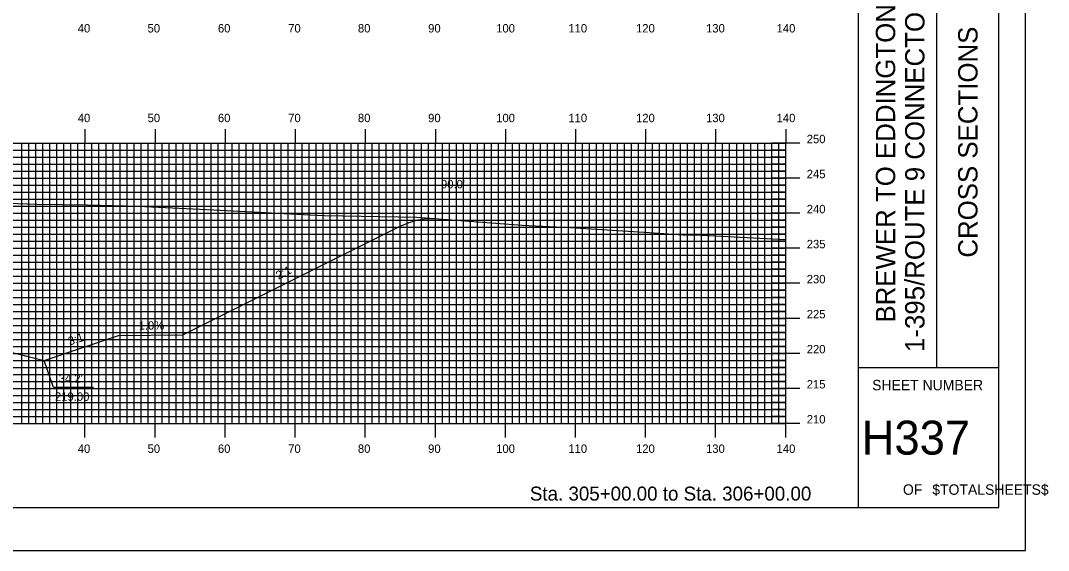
# Model space of a CAD drawing. Extents: x 1816883 to 1817226, y 442591 to 442811.
# Drawn here: x 1817079.4 to 1817226.1, y 442590.5 to 442666.2 of the extents above; entities that cross this region are included whole.
import ezdxf

# ---------------------------------------------------------------- set-up
doc = ezdxf.new("R2010")
doc.units = 0
for name, color, linetype in [('ANNOTATION', 7, 'Continuous'), ('BORDER', 7, 'Continuous'), ('D_Roadway_Centerline', 7, 'Continuous'), ('D_Roadway_SlopeLines', 7, 'Continuous'), ('D_Text_Standard', 7, 'Continuous'), ('H_V ANNOTATION', 7, 'Continuous'), ('MAJOR', 7, 'Continuous'), ('MINOR', 7, 'Continuous'), ('PLOT BOUNDARY', 7, 'Continuous'), ('S_Roadway_Centerline', 7, 'Continuous')]:
    doc.layers.add(name, color=color, linetype=linetype)

msp = doc.modelspace()

# ---------------------------------------------------------------- linework, layer by layer
at = {"layer": 'ANNOTATION'}
msp.add_lwpolyline([(1817089.8, 442613.78), (1817084.1, 442613.78), (1817082.76, 442617.67)], dxfattribs=at)
at = {"layer": 'BORDER'}
for p, q in [((1817198.99, 442596.67), (1817198.99, 442806.67)), ((1817210.17, 442616.67), (1817210.17, 442686.67)), ((1817198.99, 442616.67), (1817218.99, 442616.67))]:
    msp.add_line(p, q, dxfattribs=at)
msp.add_lwpolyline([(1816898.99, 442596.67), (1817218.99, 442596.67), (1817218.99, 442806.67), (1816898.99, 442806.67)], close=True, dxfattribs=at)
at = {"layer": 'D_Roadway_Centerline'}
msp.add_lwpolyline([(1816958.59, 442642.2), (1816959.84, 442642.08), (1816961.09, 442641.81), (1816962.34, 442641.41), (1816963.59, 442640.85), (1817002.86, 442621.22), (1817003.78, 442621.21), (1817014.41, 442617.67), (1817018.41, 442618.67), (1817028.59, 442621.21), (1817036.59, 442621.53), (1817048.59, 442621.77), (1817060.59, 442621.53), (1817068.59, 442621.21), (1817078.76, 442618.67), (1817082.76, 442617.67), (1817093.39, 442621.21), (1817102.53, 442621.3), (1817133.59, 442636.83), (1817134.84, 442637.37), (1817136.09, 442637.72), (1817137.34, 442637.9), (1817138.59, 442637.9)], dxfattribs=at)
at = {"layer": 'D_Roadway_SlopeLines'}
for points in [[(1817093.39, 442621.21), (1817102.53, 442621.3), (1817133.59, 442636.83), (1817134.84, 442637.37), (1817136.09, 442637.72), (1817137.34, 442637.9), (1817138.59, 442637.9)], [(1817068.59, 442621.21), (1817082.76, 442617.67)], [(1817082.76, 442617.67), (1817093.39, 442621.21)]]:
    msp.add_lwpolyline(points, dxfattribs=at)
at = {"layer": 'MAJOR'}
for p, q in [((1817088.59, 442650.67), (1817088.59, 442648.67)), ((1817098.59, 442650.67), (1817098.59, 442648.67)), ((1817108.59, 442650.67), (1817108.59, 442648.67)), ((1817118.59, 442650.67), (1817118.59, 442648.67)), ((1817128.59, 442650.67), (1817128.59, 442648.67)), ((1817138.59, 442650.67), (1817138.59, 442648.67)), ((1817148.59, 442650.67), (1817148.59, 442648.67)), ((1817158.59, 442650.67), (1817158.59, 442648.67)), ((1817168.59, 442650.67), (1817168.59, 442648.67)), ((1817178.59, 442650.67), (1817178.59, 442648.67)), ((1817188.59, 442650.67), (1817188.59, 442648.67)), ((1816908.59, 442648.67), (1817188.59, 442648.67)), ((1816908.59, 442648.67), (1817188.59, 442648.67)), ((1817088.59, 442608.67), (1817088.59, 442648.67)), ((1817098.59, 442608.67), (1817098.59, 442648.67)), ((1817108.59, 442608.67), (1817108.59, 442648.67)), ((1817118.59, 442608.67), (1817118.59, 442648.67)), ((1817128.59, 442608.67), (1817128.59, 442648.67)), ((1817138.59, 442608.67), (1817138.59, 442648.67)), ((1817148.59, 442608.67), (1817148.59, 442648.67)), ((1817158.59, 442608.67), (1817158.59, 442648.67)), ((1817168.59, 442608.67), (1817168.59, 442648.67)), ((1817178.59, 442608.67), (1817178.59, 442648.67)), ((1817190.59, 442648.67), (1817186.58, 442648.67)), ((1817188.59, 442608.67), (1817188.59, 442648.67)), ((1817188.59, 442608.67), (1817188.59, 442648.67)), ((1816908.59, 442643.67), (1817188.59, 442643.67)), ((1817190.59, 442643.67), (1817186.58, 442643.67)), ((1816908.59, 442638.67), (1817188.59, 442638.67)), ((1817190.59, 442638.67), (1817186.58, 442638.67)), ((1816908.59, 442633.67), (1817188.59, 442633.67)), ((1817190.59, 442633.67), (1817186.58, 442633.67)), ((1816908.59, 442628.67), (1817188.59, 442628.67)), ((1817190.59, 442628.67), (1817186.58, 442628.67)), ((1816908.59, 442623.67), (1817188.59, 442623.67)), ((1817190.59, 442623.67), (1817186.58, 442623.67)), ((1816908.59, 442618.67), (1817188.59, 442618.67)), ((1817190.59, 442618.67), (1817186.58, 442618.67)), ((1816908.59, 442613.67), (1817188.59, 442613.67)), ((1817190.59, 442613.67), (1817186.58, 442613.67)), ((1816908.59, 442608.67), (1817188.59, 442608.67)), ((1816908.59, 442608.67), (1817188.59, 442608.67)), ((1817088.59, 442606.66), (1817088.59, 442608.67)), ((1817098.59, 442606.66), (1817098.59, 442608.67)), ((1817108.59, 442606.66), (1817108.59, 442608.67)), ((1817118.59, 442606.66), (1817118.59, 442608.67)), ((1817128.59, 442606.66), (1817128.59, 442608.67)), ((1817138.59, 442606.66), (1817138.59, 442608.67)), ((1817148.59, 442606.66), (1817148.59, 442608.67)), ((1817158.59, 442606.66), (1817158.59, 442608.67)), ((1817168.59, 442606.66), (1817168.59, 442608.67)), ((1817178.59, 442606.66), (1817178.59, 442608.67)), ((1817190.59, 442608.67), (1817186.58, 442608.67)), ((1817188.59, 442606.66), (1817188.59, 442608.67))]:
    msp.add_line(p, q, dxfattribs=at)
at = {"layer": 'MINOR'}
for p, q in [((1817079.59, 442608.67), (1817079.59, 442648.67)), ((1817080.59, 442608.67), (1817080.59, 442648.67)), ((1817081.59, 442608.67), (1817081.59, 442648.67)), ((1817082.59, 442608.67), (1817082.59, 442648.67)), ((1817083.59, 442608.67), (1817083.59, 442648.67)), ((1817084.59, 442608.67), (1817084.59, 442648.67)), ((1817085.59, 442608.67), (1817085.59, 442648.67)), ((1817086.59, 442608.67), (1817086.59, 442648.67)), ((1817087.59, 442608.67), (1817087.59, 442648.67)), ((1817089.59, 442608.67), (1817089.59, 442648.67)), ((1817090.59, 442608.67), (1817090.59, 442648.67)), ((1817091.59, 442608.67), (1817091.59, 442648.67)), ((1817092.59, 442608.67), (1817092.59, 442648.67)), ((1817093.59, 442608.67), (1817093.59, 442648.67)), ((1817094.59, 442608.67), (1817094.59, 442648.67)), ((1817095.59, 442608.67), (1817095.59, 442648.67)), ((1817096.59, 442608.67), (1817096.59, 442648.67)), ((1817097.59, 442608.67), (1817097.59, 442648.67)), ((1817099.59, 442608.67), (1817099.59, 442648.67)), ((1817100.59, 442608.67), (1817100.59, 442648.67)), ((1817101.59, 442608.67), (1817101.59, 442648.67)), ((1817102.59, 442608.67), (1817102.59, 442648.67)), ((1817103.59, 442608.67), (1817103.59, 442648.67)), ((1817104.59, 442608.67), (1817104.59, 442648.67)), ((1817105.59, 442608.67), (1817105.59, 442648.67)), ((1817106.59, 442608.67), (1817106.59, 442648.67)), ((1817107.59, 442608.67), (1817107.59, 442648.67)), ((1817109.59, 442608.67), (1817109.59, 442648.67)), ((1817110.59, 442608.67), (1817110.59, 442648.67)), ((1817111.59, 442608.67), (1817111.59, 442648.67)), ((1817112.59, 442608.67), (1817112.59, 442648.67)), ((1817113.59, 442608.67), (1817113.59, 442648.67)), ((1817114.59, 442608.67), (1817114.59, 442648.67)), ((1817115.59, 442608.67), (1817115.59, 442648.67)), ((1817116.59, 442608.67), (1817116.59, 442648.67)), ((1817117.59, 442608.67), (1817117.59, 442648.67)), ((1817119.59, 442608.67), (1817119.59, 442648.67)), ((1817120.59, 442608.67), (1817120.59, 442648.67)), ((1817121.59, 442608.67), (1817121.59, 442648.67)), ((1817122.59, 442608.67), (1817122.59, 442648.67)), ((1817123.59, 442608.67), (1817123.59, 442648.67)), ((1817124.59, 442608.67), (1817124.59, 442648.67)), ((1817125.59, 442608.67), (1817125.59, 442648.67)), ((1817126.59, 442608.67), (1817126.59, 442648.67)), ((1817127.59, 442608.67), (1817127.59, 442648.67)), ((1817129.59, 442608.67), (1817129.59, 442648.67)), ((1817130.59, 442608.67), (1817130.59, 442648.67)), ((1817131.59, 442608.67), (1817131.59, 442648.67)), ((1817132.59, 442608.67), (1817132.59, 442648.67)), ((1817133.59, 442608.67), (1817133.59, 442648.67)), ((1817134.59, 442608.67), (1817134.59, 442648.67)), ((1817135.59, 442608.67), (1817135.59, 442648.67)), ((1817136.59, 442608.67), (1817136.59, 442648.67)), ((1817137.59, 442608.67), (1817137.59, 442648.67)), ((1817139.59, 442608.67), (1817139.59, 442648.67)), ((1817140.59, 442608.67), (1817140.59, 442648.67)), ((1817141.59, 442608.67), (1817141.59, 442648.67)), ((1817142.59, 442608.67), (1817142.59, 442648.67)), ((1817143.59, 442608.67), (1817143.59, 442648.67)), ((1817144.59, 442608.67), (1817144.59, 442648.67)), ((1817145.59, 442608.67), (1817145.59, 442648.67)), ((1817146.59, 442608.67), (1817146.59, 442648.67)), ((1817147.59, 442608.67), (1817147.59, 442648.67)), ((1817149.59, 442608.67), (1817149.59, 442648.67)), ((1817150.59, 442608.67), (1817150.59, 442648.67)), ((1817151.59, 442608.67), (1817151.59, 442648.67)), ((1817152.59, 442608.67), (1817152.59, 442648.67)), ((1817153.59, 442608.67), (1817153.59, 442648.67)), ((1817154.59, 442608.67), (1817154.59, 442648.67)), ((1817155.59, 442608.67), (1817155.59, 442648.67)), ((1817156.59, 442608.67), (1817156.59, 442648.67)), ((1817157.59, 442608.67), (1817157.59, 442648.67)), ((1817159.59, 442608.67), (1817159.59, 442648.67)), ((1817160.59, 442608.67), (1817160.59, 442648.67)), ((1817161.59, 442608.67), (1817161.59, 442648.67)), ((1817162.59, 442608.67), (1817162.59, 442648.67)), ((1817163.59, 442608.67), (1817163.59, 442648.67)), ((1817164.59, 442608.67), (1817164.59, 442648.67)), ((1817165.59, 442608.67), (1817165.59, 442648.67)), ((1817166.59, 442608.67), (1817166.59, 442648.67)), ((1817167.59, 442608.67), (1817167.59, 442648.67)), ((1817169.59, 442608.67), (1817169.59, 442648.67)), ((1817170.59, 442608.67), (1817170.59, 442648.67)), ((1817171.59, 442608.67), (1817171.59, 442648.67)), ((1817172.59, 442608.67), (1817172.59, 442648.67)), ((1817173.59, 442608.67), (1817173.59, 442648.67)), ((1817174.59, 442608.67), (1817174.59, 442648.67)), ((1817175.59, 442608.67), (1817175.59, 442648.67)), ((1817176.59, 442608.67), (1817176.59, 442648.67)), ((1817177.59, 442608.67), (1817177.59, 442648.67)), ((1817179.59, 442608.67), (1817179.59, 442648.67)), ((1817180.59, 442608.67), (1817180.59, 442648.67)), ((1817181.59, 442608.67), (1817181.59, 442648.67)), ((1817182.59, 442608.67), (1817182.59, 442648.67)), ((1817183.59, 442608.67), (1817183.59, 442648.67)), ((1817184.59, 442608.67), (1817184.59, 442648.67)), ((1817185.59, 442608.67), (1817185.59, 442648.67)), ((1817186.59, 442608.67), (1817186.59, 442648.67)), ((1817187.59, 442608.67), (1817187.59, 442648.67)), ((1816908.59, 442647.67), (1817188.59, 442647.67)), ((1816908.59, 442646.67), (1817188.59, 442646.67)), ((1817188.59, 442647.67), (1817186.58, 442647.67)), ((1817188.59, 442646.67), (1817186.58, 442646.67)), ((1816908.59, 442645.67), (1817188.59, 442645.67)), ((1817188.59, 442645.67), (1817186.58, 442645.67)), ((1816908.59, 442644.67), (1817188.59, 442644.67)), ((1817188.59, 442644.67), (1817186.58, 442644.67)), ((1816908.59, 442642.67), (1817188.59, 442642.67)), ((1817188.59, 442642.67), (1817186.58, 442642.67)), ((1816908.59, 442641.67), (1817188.59, 442641.67)), ((1816908.59, 442640.67), (1817188.59, 442640.67)), ((1817188.59, 442641.67), (1817186.58, 442641.67)), ((1817188.59, 442640.67), (1817186.58, 442640.67)), ((1816908.59, 442639.67), (1817188.59, 442639.67)), ((1817188.59, 442639.67), (1817186.58, 442639.67)), ((1816908.59, 442637.67), (1817188.59, 442637.67)), ((1817188.59, 442637.67), (1817186.58, 442637.67)), ((1816908.59, 442636.67), (1817188.59, 442636.67)), ((1817188.59, 442636.67), (1817186.58, 442636.67)), ((1816908.59, 442635.67), (1817188.59, 442635.67)), ((1817188.59, 442635.67), (1817186.58, 442635.67)), ((1816908.59, 442634.67), (1817188.59, 442634.67)), ((1817188.59, 442634.67), (1817186.58, 442634.67)), ((1816908.59, 442632.67), (1817188.59, 442632.67)), ((1817188.59, 442632.67), (1817186.58, 442632.67)), ((1816908.59, 442631.67), (1817188.59, 442631.67)), ((1816908.59, 442630.67), (1817188.59, 442630.67)), ((1817188.59, 442631.67), (1817186.58, 442631.67)), ((1817188.59, 442630.67), (1817186.58, 442630.67)), ((1816908.59, 442629.67), (1817188.59, 442629.67)), ((1817188.59, 442629.67), (1817186.58, 442629.67)), ((1816908.59, 442627.67), (1817188.59, 442627.67)), ((1817188.59, 442627.67), (1817186.58, 442627.67)), ((1816908.59, 442626.67), (1817188.59, 442626.67)), ((1817188.59, 442626.67), (1817186.58, 442626.67)), ((1816908.59, 442625.67), (1817188.59, 442625.67)), ((1816908.59, 442624.67), (1817188.59, 442624.67)), ((1817188.59, 442625.67), (1817186.58, 442625.67)), ((1817188.59, 442624.67), (1817186.58, 442624.67)), ((1816908.59, 442622.67), (1817188.59, 442622.67)), ((1816908.59, 442621.67), (1817188.59, 442621.67)), ((1817188.59, 442622.67), (1817186.58, 442622.67)), ((1817188.59, 442621.67), (1817186.58, 442621.67)), ((1816908.59, 442620.67), (1817188.59, 442620.67)), ((1817188.59, 442620.67), (1817186.58, 442620.67)), ((1816908.59, 442619.67), (1817188.59, 442619.67)), ((1817188.59, 442619.67), (1817186.58, 442619.67)), ((1816908.59, 442617.67), (1817188.59, 442617.67)), ((1817188.59, 442617.67), (1817186.58, 442617.67)), ((1816908.59, 442616.67), (1817188.59, 442616.67)), ((1816908.59, 442615.67), (1817188.59, 442615.67)), ((1817188.59, 442616.67), (1817186.58, 442616.67)), ((1817188.59, 442615.67), (1817186.58, 442615.67)), ((1816908.59, 442614.67), (1817188.59, 442614.67)), ((1817188.59, 442614.67), (1817186.58, 442614.67)), ((1816908.59, 442612.67), (1817188.59, 442612.67)), ((1816908.59, 442611.67), (1817188.59, 442611.67)), ((1817188.59, 442612.67), (1817186.58, 442612.67)), ((1817188.59, 442611.67), (1817186.58, 442611.67)), ((1816908.59, 442610.67), (1817188.59, 442610.67)), ((1817188.59, 442610.67), (1817186.58, 442610.67)), ((1816908.59, 442609.67), (1817188.59, 442609.67)), ((1817188.59, 442609.67), (1817186.58, 442609.67))]:
    msp.add_line(p, q, dxfattribs=at)
at = {"layer": 'PLOT BOUNDARY'}
msp.add_lwpolyline([(1816882.8, 442590.55), (1817222.8, 442590.55), (1817222.8, 442810.55), (1816882.8, 442810.55)], close=True, dxfattribs=at)
at = {"layer": 'S_Roadway_Centerline'}
msp.add_lwpolyline([(1817071.91, 442640.29), (1817081.78, 442639.98), (1817088.97, 442639.89), (1817096.13, 442639.67), (1817106.96, 442639.15), (1817120.68, 442638.44), (1817122.78, 442638.35), (1817135.94, 442638.09), (1817139.67, 442637.82), (1817151, 442636.96), (1817157.79, 442636.65), (1817169.16, 442635.9), (1817173.89, 442635.58), (1817176.61, 442635.53), (1817188.59, 442634.93)], dxfattribs=at)

# ---------------------------------------------------------------- texts
at = {"layer": 'ANNOTATION'}
for s, rotation, p in [('2:1', 26.5651, (1817116.2, 442629.17)), ('1.0%', 0.5729, (1817096.25, 442622.04)), ('3:1', 18.4349, (1817086.41, 442619.79))]:
    msp.add_text(s, height=1.2, rotation=rotation, dxfattribs=at).set_placement(p)
for s, p in [("34.2'", (1817084.84, 442614.5)), ('219.00', (1817084.31, 442611.9))]:
    msp.add_text(s, height=1.2, dxfattribs=at).set_placement(p)
at = {"layer": 'BORDER'}
for s, p in [('1-395/ROUTE 9 CONNECTOR', (1817208.39, 442618.87)), ('BREWER TO EDDINGTON', (1817204.21, 442623.07)), ('CROSS SECTIONS', (1817215.96, 442632.34))]:
    msp.add_text(s, height=2.7557, rotation=90, dxfattribs=at).set_placement(p)
for s, height, p in [('SHEET NUMBER', 1.4905, (1817200.92, 442613.4)), ('H337', 4.839, (1817199.43, 442604.23)), ('OF', 1.491, (1817205.32, 442598.49)), ('$TOTALSHEETS$', 1.4905, (1817209.5, 442598.49))]:
    msp.add_text(s, height=height, dxfattribs=at).set_placement(p)
at = {"layer": 'D_Text_Standard'}
msp.add_text("90.0'", height=1.2, dxfattribs=at).set_placement((1817139.4, 442642.23))
at = {"layer": 'H_V ANNOTATION'}
for s, height, p in [('40', 1.2, (1817087.56, 442664.47)), ('50', 1.2, (1817097.52, 442664.47)), ('60', 1.2, (1817107.56, 442664.47)), ('70', 1.2, (1817117.59, 442664.47)), ('80', 1.2, (1817127.54, 442664.47)), ('90', 1.2, (1817137.56, 442664.47)), ('100', 1.2, (1817147.27, 442664.47)), ('110', 1.2, (1817157.57, 442664.47)), ('120', 1.2, (1817167.23, 442664.47)), ('130', 1.2, (1817177.22, 442664.47)), ('140', 1.2, (1817187.29, 442664.47)), ('40', 1.2, (1817087.56, 442651.67)), ('50', 1.2, (1817097.52, 442651.67)), ('60', 1.2, (1817107.56, 442651.67)), ('70', 1.2, (1817117.59, 442651.67)), ('80', 1.2, (1817127.54, 442651.67)), ('90', 1.2, (1817137.56, 442651.67)), ('100', 1.2, (1817147.27, 442651.67)), ('110', 1.2, (1817157.57, 442651.67)), ('120', 1.2, (1817167.23, 442651.67)), ('130', 1.2, (1817177.22, 442651.67)), ('140', 1.2, (1817187.29, 442651.67)), ('250', 1.2, (1817191.59, 442648.67)), ('245', 1.2, (1817191.59, 442643.67)), ('240', 1.2, (1817191.59, 442638.67)), ('235', 1.2, (1817191.59, 442633.67)), ('230', 1.2, (1817191.59, 442628.67)), ('225', 1.2, (1817191.59, 442623.67)), ('220', 1.2, (1817191.59, 442618.67)), ('215', 1.2, (1817191.59, 442613.67)), ('210', 1.2, (1817191.59, 442608.67)), ('40', 1.2, (1817087.56, 442604.47)), ('50', 1.2, (1817097.52, 442604.47)), ('60', 1.2, (1817107.56, 442604.47)), ('70', 1.2, (1817117.59, 442604.47)), ('80', 1.2, (1817127.54, 442604.47)), ('90', 1.2, (1817137.56, 442604.47)), ('100', 1.2, (1817147.27, 442604.47)), ('110', 1.2, (1817157.57, 442604.47)), ('120', 1.2, (1817167.23, 442604.47)), ('130', 1.2, (1817177.22, 442604.47)), ('140', 1.2, (1817187.29, 442604.47)), ('Sta. 305+00.00 to Sta. 306+00.00', 2.0004, (1817152.08, 442597.66))]:
    msp.add_text(s, height=height, dxfattribs=at).set_placement(p)

doc.saveas('drawing.dxf')
